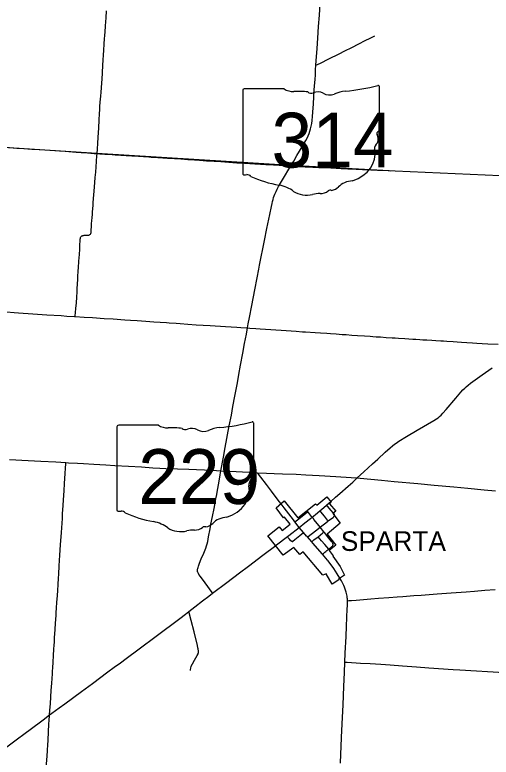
# Model space of a CAD drawing. Extents: x 9078 to 9739, y 4248 to 4966.
# Drawn here: x 9527 to 9587.6, y 4332.5 to 4427 of the extents above; entities that cross this region are included whole.
import ezdxf

# ---------------------------------------------------------------- set-up
doc = ezdxf.new("R2010")
doc.units = 0
for name, color, linetype in [('GM_X_City_Street', 7, 'Continuous'), ('GM_X_Corporation', 7, 'Continuous'), ('GM_X_Corporation_Text', 7, 'Continuous'), ('GM_X_County_Road', 7, 'Continuous'), ('GM_X_State_Route', 7, 'Continuous'), ('GM_X_State_Shield', 7, 'Continuous'), ('GM_X_Township', 7, 'Continuous'), ('GM_X_Township_Road', 7, 'Continuous')]:
    doc.layers.add(name, color=color, linetype=linetype)

msp = doc.modelspace()

# ---------------------------------------------------------------- linework, layer by layer
at = {"layer": 'GM_X_City_Street'}
for points in [[(9567.668, 4363.262), (9567.67, 4363.274), (9567.671, 4363.287), (9567.672, 4363.296), (9567.672, 4363.301), (9567.672, 4363.312), (9567.671, 4363.327), (9567.667, 4363.353), (9567.658, 4363.386), (9567.651, 4363.406), (9567.64, 4363.436), (9567.631, 4363.452), (9567.624, 4363.467), (9567.608, 4363.493), (9567.581, 4363.53), (9567.548, 4363.574), (9567.257, 4363.898), (9566.779, 4364.431), (9566.642, 4364.585)], [(9562.627, 4362.464), (9563.108, 4362.841), (9564.229, 4363.711), (9564.233, 4363.714), (9564.24, 4363.718), (9564.247, 4363.72), (9564.252, 4363.722), (9564.256, 4363.723), (9564.262, 4363.725), (9564.275, 4363.724)], [(9564.802, 4363.05), (9564.75, 4363.118), (9564.337, 4363.661), (9564.306, 4363.698), (9564.303, 4363.703), (9564.299, 4363.707), (9564.291, 4363.714), (9564.288, 4363.717), (9564.284, 4363.72), (9564.275, 4363.724)], [(9565.839, 4361.78), (9565.709, 4361.944), (9565.05, 4362.771), (9564.983, 4362.857), (9564.942, 4362.904), (9564.905, 4362.946), (9564.861, 4362.993), (9564.802, 4363.05)], [(9566.862, 4362.566), (9566.786, 4362.66), (9566.38, 4363.162), (9565.913, 4363.719), (9565.792, 4363.863)], [(9566.862, 4362.566), (9567.153, 4362.782), (9567.481, 4363.024), (9567.565, 4363.102), (9567.584, 4363.121), (9567.608, 4363.147), (9567.624, 4363.169), (9567.644, 4363.204), (9567.652, 4363.219), (9567.657, 4363.231), (9567.66, 4363.24), (9567.665, 4363.253), (9567.668, 4363.262)], [(9565.839, 4361.78), (9565.867, 4361.801), (9566.377, 4362.192), (9566.761, 4362.491), (9566.862, 4362.566)], [(9564.213, 4360.524), (9564.322, 4360.607), (9565.226, 4361.3), (9565.839, 4361.78)], [(9565.57, 4360.564), (9566.192, 4361.065), (9566.315, 4361.177)], [(9566.315, 4361.177), (9565.839, 4361.78)], [(9567.471, 4359.47), (9567.478, 4359.494), (9567.483, 4359.523), (9567.485, 4359.557), (9567.484, 4359.588), (9567.478, 4359.64), (9567.471, 4359.673), (9567.46, 4359.704), (9567.443, 4359.737), (9567.42, 4359.778), (9567.368, 4359.847), (9567.254, 4359.999), (9567.12, 4360.168), (9566.767, 4360.608), (9566.639, 4360.775), (9566.417, 4361.053), (9566.315, 4361.177)], [(9562.266, 4359.955), (9562.243, 4359.957), (9562.23, 4359.96), (9562.213, 4359.965), (9562.203, 4359.968), (9562.191, 4359.974), (9562.178, 4359.981), (9562.169, 4359.987), (9562.152, 4360), (9562.132, 4360.017), (9562.103, 4360.044), (9562.086, 4360.061), (9562.067, 4360.083), (9561.939, 4360.23), (9561.786, 4360.427), (9561.663, 4360.585)], [(9562.266, 4359.955), (9562.28, 4359.956), (9562.294, 4359.956), (9562.31, 4359.958), (9562.323, 4359.961), (9562.33, 4359.962), (9562.337, 4359.965), (9562.345, 4359.97), (9562.35, 4359.973), (9562.357, 4359.978), (9562.363, 4359.983), (9562.629, 4360.207), (9563.236, 4360.701), (9563.71, 4361.106)], [(9564.758, 4359.906), (9564.86, 4359.989), (9565.051, 4360.146), (9565.57, 4360.564)], [(9566.921, 4358.981), (9566.436, 4359.55), (9565.997, 4360.043), (9565.8, 4360.283), (9565.57, 4360.564)], [(9566.921, 4358.981), (9567.329, 4359.297), (9567.43, 4359.39), (9567.454, 4359.424), (9567.462, 4359.444), (9567.471, 4359.47)], [(9566.124, 4358.332), (9566.262, 4358.44), (9566.445, 4358.595), (9566.567, 4358.699), (9566.702, 4358.809), (9566.921, 4358.981)]]:
    msp.add_lwpolyline(points, dxfattribs=at)
at = {"layer": 'GM_X_Corporation'}
msp.add_lwpolyline([(9566.167, 4355.686), (9563.694, 4358.633), (9563.248, 4358.28), (9562.487, 4359.202), (9561.141, 4358.229), (9559.186, 4360.654), (9560.641, 4361.807), (9561.01, 4361.336), (9562.002, 4362.166), (9561.309, 4363.066), (9561.176, 4362.96), (9560.225, 4364.231), (9561.267, 4365.121), (9563.004, 4362.976), (9565.229, 4364.736), (9565.409, 4364.565), (9566.691, 4365.635), (9567.249, 4364.945), (9567.035, 4364.752), (9567.838, 4363.812), (9567.455, 4363.506), (9568.402, 4362.273), (9566.727, 4360.87), (9567.847, 4359.474), (9567.002, 4358.799), (9567.482, 4358.112), (9567.441, 4358.082), (9568.396, 4356.773), (9568.953, 4355.676), (9568.167, 4355.142), (9568.209, 4355.08), (9567.382, 4354.519), (9566.59, 4355.84)], close=True, dxfattribs=at)
at = {"layer": 'GM_X_County_Road'}
for points in [[(9525.856, 4410.11), (9527.247, 4410.016), (9528.147, 4409.955), (9529.128, 4409.889), (9530.082, 4409.829), (9530.787, 4409.783), (9531.457, 4409.737), (9532.684, 4409.66), (9533.39, 4409.614), (9533.874, 4409.572), (9534.772, 4409.505), (9535.427, 4409.455), (9536.245, 4409.394), (9537.063, 4409.334), (9537.447, 4409.309)], [(9537.447, 4409.309), (9537.799, 4409.287), (9538.454, 4409.249), (9539.354, 4409.19), (9539.763, 4409.165), (9541.155, 4409.074), (9541.891, 4409.026), (9542.71, 4408.97), (9543.364, 4408.927), (9544.018, 4408.886), (9544.345, 4408.865), (9545.164, 4408.814), (9546.392, 4408.733), (9547.292, 4408.681), (9548.121, 4408.629), (9549.012, 4408.569), (9549.83, 4408.515), (9550.485, 4408.471), (9551.386, 4408.412), (9552.368, 4408.342), (9553.186, 4408.286), (9555.233, 4408.157), (9556.215, 4408.088), (9557.525, 4408.003), (9558.917, 4407.925), (9559.9, 4407.869), (9561.293, 4407.792), (9562.098, 4407.735)], [(9570.559, 4368.037), (9571.408, 4368.831), (9572.5, 4369.824), (9573.161, 4370.439), (9574.126, 4371.328), (9574.736, 4371.876), (9575.048, 4372.141), (9575.305, 4372.341), (9575.505, 4372.481), (9575.851, 4372.698), (9576.828, 4373.302), (9578.163, 4374.103), (9580.285, 4375.35), (9580.636, 4375.564), (9580.84, 4375.704), (9581.035, 4375.857), (9581.216, 4376.026), (9581.441, 4376.266), (9581.869, 4376.765), (9583.094, 4378.198), (9583.735, 4378.945), (9584.004, 4379.252), (9584.231, 4379.484), (9584.41, 4379.651), (9584.659, 4379.861), (9584.984, 4380.11), (9586.453, 4381.158), (9587.726, 4382.057)], [(9531.394, 4337.879), (9531.443, 4338.436), (9531.504, 4339.335), (9531.618, 4341.006), (9531.681, 4341.908), (9531.756, 4343.098), (9531.783, 4343.506), (9531.805, 4343.834), (9531.861, 4344.651), (9531.909, 4345.387), (9531.958, 4346.288), (9531.983, 4346.697), (9532.013, 4347.187), (9532.043, 4347.678), (9532.118, 4348.742), (9532.176, 4349.56), (9532.239, 4350.541), (9532.26, 4350.868), (9532.305, 4351.521), (9532.348, 4352.176), (9532.408, 4353.076), (9532.456, 4353.73), (9532.501, 4354.466), (9532.541, 4355.285), (9532.568, 4355.776), (9532.622, 4356.841), (9532.71, 4358.233), (9532.804, 4359.541), (9532.908, 4361.096), (9533.032, 4362.895), (9533.07, 4363.468), (9533.139, 4364.532), (9533.19, 4365.268), (9533.267, 4366.413), (9533.325, 4367.313), (9533.396, 4368.623), (9533.441, 4369.297), (9533.474, 4369.85), (9533.482, 4369.99)], [(9530.696, 4326.773), (9530.739, 4327.396), (9530.805, 4328.295), (9530.863, 4329.074), (9530.923, 4330.094), (9530.994, 4331.155), (9531.027, 4331.646), (9531.095, 4332.628), (9531.15, 4333.375), (9531.192, 4334.109), (9531.22, 4334.592), (9531.282, 4335.819), (9531.329, 4336.637), (9531.359, 4337.291), (9531.379, 4337.7), (9531.394, 4337.879)]]:
    msp.add_lwpolyline(points, dxfattribs=at)
at = {"layer": 'GM_X_State_Route'}
for points in [[(9553.215, 4368.964), (9553.535, 4370.698), (9553.766, 4371.907), (9554.279, 4374.65), (9554.537, 4376.02), (9554.746, 4377.15), (9554.988, 4378.44), (9555.301, 4380.134), (9555.498, 4381.183), (9555.721, 4382.393), (9556.001, 4383.924), (9556.231, 4385.132), (9556.462, 4386.341), (9556.606, 4387.127), (9556.697, 4387.631), (9556.846, 4388.436), (9557.14, 4389.968), (9557.531, 4391.981), (9557.815, 4393.513), (9558.021, 4394.594), (9558.129, 4395.128), (9558.758, 4398.246), (9559.058, 4399.775), (9559.307, 4400.98), (9559.42, 4401.565), (9559.631, 4402.584), (9559.711, 4402.956), (9559.769, 4403.229), (9559.839, 4403.472), (9559.913, 4403.723), (9559.985, 4403.925), (9560.07, 4404.143), (9560.154, 4404.34), (9560.227, 4404.491), (9560.371, 4404.794), (9560.54, 4405.117), (9561.033, 4405.968), (9562.098, 4407.735), (9562.469, 4408.362), (9562.888, 4409.066), (9563.227, 4409.628), (9563.774, 4410.543), (9564.015, 4410.971), (9564.165, 4411.262), (9564.304, 4411.558), (9564.428, 4411.861), (9564.536, 4412.169), (9564.628, 4412.482), (9564.702, 4412.801), (9564.76, 4413.122), (9564.817, 4413.527), (9564.863, 4414.017), (9564.908, 4414.589), (9564.975, 4415.652), (9565.09, 4417.371), (9565.13, 4417.944), (9565.186, 4418.762), (9565.225, 4419.334), (9565.265, 4419.983), (9565.304, 4420.551), (9565.344, 4421.127), (9565.45, 4422.682), (9565.537, 4423.991), (9565.638, 4425.464), (9565.734, 4426.937), (9565.882, 4429.147)], [(9526.297, 4370.368), (9528.673, 4370.27), (9530.312, 4370.193), (9532.195, 4370.084), (9533.482, 4369.99), (9533.831, 4369.966), (9534.977, 4369.898), (9535.714, 4369.861), (9537.022, 4369.781), (9538.578, 4369.691), (9539.724, 4369.625), (9541.444, 4369.544), (9543.082, 4369.444), (9544.555, 4369.343), (9545.455, 4369.289), (9546.192, 4369.251), (9547.666, 4369.195), (9549.142, 4369.138), (9552.093, 4369.018), (9553.215, 4368.964)], [(9553.215, 4368.964), (9555.146, 4368.858), (9557.613, 4368.721), (9557.807, 4368.71)], [(9557.807, 4368.71), (9559.007, 4368.647), (9559.99, 4368.607), (9561.056, 4368.565), (9562.776, 4368.499), (9563.995, 4368.441), (9565.703, 4368.348), (9567.831, 4368.22), (9569.794, 4368.089), (9570.559, 4368.037)], [(9560.859, 4364.764), (9560.639, 4365.053), (9559.648, 4366.363), (9559.002, 4367.213), (9558.301, 4368.124), (9557.984, 4368.505), (9557.807, 4368.71)], [(9567.189, 4365.052), (9567.788, 4365.578), (9568.341, 4366.076), (9569.4, 4367.001), (9569.995, 4367.521), (9570.21, 4367.712), (9570.39, 4367.878), (9570.559, 4368.037)], [(9570.559, 4368.037), (9570.939, 4368.01), (9573.634, 4367.747), (9575.269, 4367.601), (9578.285, 4367.315), (9580.327, 4367.126), (9582.858, 4366.892), (9584.651, 4366.727), (9586.691, 4366.542), (9588.159, 4366.411)], [(9566.971, 4364.87), (9567.189, 4365.052)], [(9560.184, 4359.448), (9560.294, 4359.529), (9561.663, 4360.585), (9561.846, 4360.727), (9563.168, 4361.749), (9563.895, 4362.321), (9564.599, 4362.887), (9564.802, 4363.05), (9565.239, 4363.401), (9565.792, 4363.863), (9566.311, 4364.297), (9566.642, 4364.585), (9566.971, 4364.87)], [(9566.851, 4357.486), (9566.787, 4357.565), (9566.124, 4358.332), (9564.922, 4359.719), (9564.758, 4359.906), (9564.213, 4360.524), (9564.113, 4360.637), (9563.71, 4361.106), (9563.168, 4361.749), (9562.627, 4362.464), (9562.453, 4362.694), (9561.271, 4364.248), (9560.859, 4364.764)], [(9525.974, 4333.835), (9527.164, 4334.711), (9528.282, 4335.543), (9528.938, 4336.036), (9530.577, 4337.271), (9531.394, 4337.879), (9531.696, 4338.103), (9532.623, 4338.781), (9533.355, 4339.308), (9535.47, 4340.866), (9536.853, 4341.892), (9538.836, 4343.352), (9539.626, 4343.939), (9540.422, 4344.518), (9541.145, 4345.059), (9542.802, 4346.288), (9544.98, 4347.898), (9547.992, 4350.153), (9548.702, 4350.712), (9549.112, 4351.027), (9549.898, 4351.653), (9550.869, 4352.413), (9551.651, 4353.013), (9552.141, 4353.382), (9553.95, 4354.742), (9555.588, 4355.982), (9556.699, 4356.829), (9558.542, 4358.208), (9560.184, 4359.448)], [(9568.362, 4355.271), (9568.005, 4355.852), (9567.566, 4356.517), (9567.354, 4356.829), (9567.075, 4357.208), (9566.851, 4357.486)], [(9568.426, 4331.738), (9568.464, 4332.885), (9568.493, 4333.867), (9568.55, 4335.011), (9568.623, 4336.731), (9568.747, 4339.188), (9568.847, 4341.482), (9568.919, 4343.284), (9568.98, 4344.607), (9569.033, 4345.741), (9569.134, 4347.87), (9569.186, 4349.181), (9569.29, 4351.385), (9569.308, 4351.768), (9569.312, 4352.033), (9569.319, 4352.331), (9569.319, 4352.417), (9569.319, 4352.444), (9569.316, 4352.535), (9569.305, 4352.659), (9569.287, 4352.799), (9569.262, 4352.975), (9569.226, 4353.156), (9569.186, 4353.338), (9569.141, 4353.52), (9569.072, 4353.754), (9568.94, 4354.143), (9568.861, 4354.334), (9568.777, 4354.521), (9568.657, 4354.757), (9568.55, 4354.959), (9568.362, 4355.271)]]:
    msp.add_lwpolyline(points, dxfattribs=at)
at = {"layer": 'GM_X_State_Shield'}
for p, q in [((9555.977, 4417.368), (9555.977, 4406.802)), ((9561.245, 4417.55), (9556.149, 4417.55)), ((9573.379, 4412.285), (9573.379, 4417.812)), ((9573.378, 4412.286), (9573.379, 4412.285)), ((9539.983, 4374.556), (9539.983, 4363.99)), ((9545.251, 4374.738), (9540.155, 4374.738)), ((9557.385, 4369.473), (9557.385, 4375)), ((9557.384, 4369.474), (9557.385, 4369.473))]:
    msp.add_line(p, q, dxfattribs=at)
for centre, major_axis, start_param, end_param in [((9567.18, 4431.956), (18.455, 0), 4.814394, 5.042369), ((9573.186, 4417.835), (0.194, 0), 6.141152, 7.989035), ((9556.177, 4417.391), (0.202, 0), 1.712693, 3.28349), ((9562.459, 4418.777), (1.955, 0), 4.042523, 4.731795), ((9563.107, 4411.618), (7.02, 0), 1.404758, 1.657858), ((9564.701, 4417.446), (0.564, 0), 3.836095, 5.185415), ((9565.529, 4416.224), (1.173, 0), 0.950623, 2.079405), ((9567.043, 4417.899), (1.411, 0), 4.081561, 5.145723), ((9569.534, 4414.323), (3.713, 0), 1.699011, 2.107814), ((9573.173, 4412.263), (0.207, 0), 5.05454, 6.418171), ((9573.335, 4411.879), (0.3, 0), 1.883978, 3.671073), ((9571.427, 4411.18), (1.8, 0), 5.934695, 6.695948), ((9574.073, 4409.971), (1.309, 0), 2.387724, 3.262537), ((9568.214, 4409.268), (4.616, 0), 5.101752, 6.440018), ((9556.179, 4406.779), (0.203, 0), 3.00124, 4.508301), ((9556.209, 4407.86), (1.552, 0), 4.665946, 4.897461), ((9556.527, 4406.192), (0.56, 0), 0.519207, 1.627899), ((9563.593, 4415.686), (13.327, 0), 4.195997, 4.488961), ((9570.161, 4403.835), (2.528, 0), 1.647645, 2.488434), ((9559.62, 4402.055), (4.17, 0), 0.823519, 1.323587), ((9567.127, 4404.325), (0.397, 0), 1.147584, 2.315152), ((9566.958, 4405.778), (1.491, 0), 4.937069, 5.64225), ((9564.129, 4406.14), (2.646, 0), 4.026481, 4.996735), ((9565.658, 4402.487), (2.174, 0), 1.495662, 1.94098), ((9565.852, 4405.349), (1.41, 0), 4.691044, 5.507374), ((9540.183, 4374.579), (0.202, 0), 1.712693, 3.28349), ((9546.465, 4375.965), (1.955, 0), 4.042523, 4.731795), ((9547.113, 4368.806), (7.02, 0), 1.404758, 1.657858), ((9549.535, 4373.412), (1.173, 0), 0.950623, 2.079405), ((9553.54, 4371.511), (3.713, 0), 1.699011, 2.107814), ((9551.187, 4389.144), (18.455, 0), 4.814394, 5.042369), ((9557.192, 4375.023), (0.194, 0), 6.141152, 7.989035), ((9548.707, 4374.634), (0.564, 0), 3.836095, 5.185415), ((9551.049, 4375.087), (1.411, 0), 4.081561, 5.145723), ((9557.341, 4369.067), (0.3, 0), 1.883978, 3.671073), ((9555.433, 4368.368), (1.8, 0), 5.934695, 6.695948), ((9557.179, 4369.451), (0.207, 0), 5.05454, 6.418171), ((9558.079, 4367.16), (1.309, 0), 2.387724, 3.262537), ((9552.22, 4366.456), (4.616, 0), 5.101752, 6.440018), ((9540.185, 4363.967), (0.203, 0), 3.00124, 4.508301), ((9540.215, 4365.048), (1.552, 0), 4.665946, 4.897461), ((9540.533, 4363.38), (0.56, 0), 0.519207, 1.627899), ((9547.599, 4372.874), (13.327, 0), 4.195997, 4.488961), ((9543.626, 4359.243), (4.17, 0), 0.823519, 1.323587), ((9550.964, 4362.966), (1.491, 0), 4.937069, 5.64225), ((9554.167, 4361.024), (2.528, 0), 1.647645, 2.488434), ((9548.135, 4363.328), (2.646, 0), 4.026481, 4.996735), ((9549.664, 4359.675), (2.174, 0), 1.495662, 1.94098), ((9549.858, 4362.537), (1.41, 0), 4.691044, 5.507374), ((9551.133, 4361.513), (0.397, 0), 1.147584, 2.315152)]:
    msp.add_ellipse(centre, major_axis=major_axis, ratio=0.8, start_param=start_param, end_param=end_param, dxfattribs=at)
at = {"layer": 'GM_X_Township'}
msp.add_lwpolyline([(9646.564, 4403.186), (9632.593, 4403.992), (9619.889, 4404.725), (9619.129, 4404.769), (9590.635, 4406.413), (9575.396, 4407.069), (9562.089, 4407.805), (9537.409, 4409.337), (9510.323, 4411.058), (9511.38, 4427.966), (9511.83, 4435.772), (9511.888, 4436.239), (9513.121, 4453.992), (9514.674, 4478.861), (9516.207, 4506.231), (9517.263, 4528.671), (9517.499, 4532.736), (9518.307, 4546.633)], dxfattribs=at)
at = {"layer": 'GM_X_Township_Road'}
for points in [[(9537.447, 4409.309), (9537.495, 4409.895), (9537.539, 4410.632), (9537.587, 4411.369), (9537.664, 4412.597), (9537.726, 4413.58), (9537.771, 4414.399), (9537.798, 4414.891), (9537.821, 4415.3), (9537.859, 4415.87), (9537.886, 4416.223), (9537.913, 4416.627), (9537.949, 4417.113), (9538.035, 4418.292), (9538.079, 4418.83), (9538.134, 4419.542), (9538.203, 4420.601), (9538.236, 4421.175), (9538.283, 4421.911), (9538.315, 4422.401), (9538.367, 4423.302), (9538.404, 4423.876), (9538.435, 4424.367), (9538.46, 4424.775), (9538.516, 4425.591), (9538.553, 4426.081), (9538.589, 4426.572), (9538.649, 4427.473)], [(9565.304, 4420.551), (9565.869, 4420.82), (9566.944, 4421.35), (9568.267, 4422.009), (9568.999, 4422.382), (9569.876, 4422.83), (9570.754, 4423.278), (9571.558, 4423.688), (9572.222, 4424.004), (9572.793, 4424.277)], [(9534.673, 4388.579), (9534.682, 4388.684), (9534.719, 4389.092), (9534.758, 4389.583), (9534.81, 4390.32), (9534.857, 4391.058), (9534.897, 4391.713), (9534.923, 4392.122), (9534.991, 4393.35), (9535.017, 4393.76), (9535.049, 4394.25), (9535.09, 4394.905), (9535.126, 4395.478), (9535.138, 4395.642), (9535.164, 4396.052), (9535.192, 4396.46), (9535.236, 4397.142), (9535.272, 4397.735), (9535.301, 4398.158), (9535.315, 4398.403), (9535.335, 4398.566), (9535.355, 4398.646), (9535.39, 4398.718), (9535.439, 4398.782), (9535.502, 4398.831), (9535.575, 4398.868), (9535.655, 4398.892), (9535.736, 4398.906), (9535.819, 4398.913), (9536.229, 4398.911), (9536.313, 4398.914), (9536.394, 4398.927), (9536.467, 4398.957), (9536.535, 4399), (9536.593, 4399.06), (9536.64, 4399.136), (9536.687, 4399.268), (9536.696, 4399.367), (9536.714, 4399.646), (9536.728, 4399.938), (9536.741, 4400.253), (9536.759, 4400.513), (9536.773, 4400.66), (9536.781, 4400.802), (9536.81, 4401.124), (9536.855, 4401.62), (9536.87, 4401.863), (9536.938, 4402.762), (9536.944, 4402.844), (9536.966, 4403.09), (9537.053, 4404.071), (9537.131, 4405.054), (9537.226, 4406.281), (9537.281, 4406.932), (9537.386, 4408.323), (9537.434, 4409.06), (9537.442, 4409.224), (9537.447, 4409.309)], [(9562.098, 4407.735), (9562.704, 4407.693), (9563.195, 4407.667), (9563.933, 4407.633), (9564.916, 4407.588), (9565.654, 4407.554), (9566.31, 4407.527), (9567.211, 4407.481), (9568.522, 4407.423), (9569.341, 4407.386), (9570.406, 4407.341), (9571.226, 4407.308), (9572.291, 4407.259), (9573.124, 4407.219), (9573.766, 4407.188), (9574.503, 4407.146), (9574.817, 4407.133)], [(9520.906, 4389.467), (9521.005, 4389.462), (9521.496, 4389.441), (9522.15, 4389.407), (9522.559, 4389.384), (9523.296, 4389.336), (9523.951, 4389.295), (9525.015, 4389.222), (9525.915, 4389.161), (9526.897, 4389.098), (9527.47, 4389.063), (9529.27, 4388.937), (9531.071, 4388.814), (9532.871, 4388.691), (9533.607, 4388.64), (9534.59, 4388.583), (9534.673, 4388.579)], [(9534.673, 4388.579), (9535.818, 4388.505), (9536.882, 4388.441), (9538.356, 4388.347), (9539.502, 4388.27), (9540.975, 4388.167), (9541.712, 4388.12)], [(9541.712, 4388.12), (9542.53, 4388.068), (9543.675, 4387.986), (9544.657, 4387.918), (9545.475, 4387.861), (9546.294, 4387.808), (9546.621, 4387.784), (9547.52, 4387.717), (9548.011, 4387.682), (9548.992, 4387.613), (9550.053, 4387.54), (9550.948, 4387.485), (9551.845, 4387.424), (9553.775, 4387.302), (9554.524, 4387.252), (9555.243, 4387.212), (9555.736, 4387.177), (9556.45, 4387.137), (9556.606, 4387.127)], [(9556.606, 4387.127), (9556.892, 4387.108), (9557.636, 4387.051), (9558.219, 4387.021), (9558.898, 4386.976), (9560.869, 4386.841), (9562.794, 4386.7), (9563.608, 4386.645), (9563.958, 4386.619), (9565.192, 4386.539), (9565.875, 4386.494), (9566.7, 4386.444), (9567.167, 4386.414), (9567.886, 4386.366), (9568.625, 4386.313), (9569.128, 4386.278), (9569.887, 4386.223), (9570.601, 4386.173), (9571.46, 4386.112), (9572.215, 4386.061), (9572.542, 4386.04), (9572.952, 4386.016), (9573.524, 4385.977), (9574.259, 4385.924), (9574.994, 4385.873), (9575.403, 4385.847), (9575.812, 4385.823), (9576.63, 4385.772), (9577.612, 4385.71), (9578.021, 4385.684), (9578.512, 4385.659), (9578.921, 4385.633), (9579.412, 4385.597), (9580.066, 4385.552), (9580.558, 4385.526), (9581.213, 4385.492), (9581.541, 4385.472), (9581.949, 4385.448), (9582.765, 4385.4), (9583.256, 4385.367), (9583.828, 4385.326), (9584.483, 4385.285), (9585.22, 4385.241), (9585.792, 4385.201), (9586.446, 4385.151), (9587.183, 4385.11), (9588.494, 4385.045)], [(9552.141, 4353.382), (9552.086, 4353.457), (9551.189, 4354.693), (9550.605, 4355.479), (9550.418, 4355.749), (9550.335, 4355.888), (9550.3, 4355.96), (9550.27, 4356.034), (9550.248, 4356.11), (9550.233, 4356.186), (9550.229, 4356.266), (9550.23, 4356.345), (9550.24, 4356.425), (9550.255, 4356.505), (9550.294, 4356.663), (9550.343, 4356.818), (9550.487, 4357.201), (9550.709, 4357.73), (9551.032, 4358.486), (9551.279, 4359.096), (9551.389, 4359.407), (9551.459, 4359.645), (9551.534, 4359.966), (9551.648, 4360.53), (9551.834, 4361.583), (9551.935, 4362.148), (9552.123, 4363.115), (9552.33, 4364.163), (9552.567, 4365.367), (9552.676, 4365.938), (9552.783, 4366.502), (9552.952, 4367.39), (9553.126, 4368.439), (9553.215, 4368.964)], [(9569.319, 4352.417), (9569.503, 4352.428), (9569.83, 4352.448), (9570.403, 4352.495), (9572.287, 4352.644), (9573.269, 4352.724), (9574.58, 4352.824), (9575.643, 4352.914), (9576.38, 4352.972), (9577.773, 4353.078), (9578.674, 4353.142), (9580.721, 4353.299), (9582.524, 4353.429), (9584.408, 4353.566), (9585.473, 4353.645), (9586.783, 4353.749), (9588.094, 4353.849)], [(9549.339, 4343.515), (9549.343, 4343.679), (9549.365, 4343.84), (9549.437, 4344.073), (9549.574, 4344.37), (9549.86, 4344.867), (9550.19, 4345.434), (9550.296, 4345.656), (9550.315, 4345.699), (9550.328, 4345.731), (9550.337, 4345.761), (9550.345, 4345.793), (9550.351, 4345.819), (9550.356, 4345.861), (9550.358, 4345.907), (9550.358, 4345.94), (9550.356, 4345.97), (9550.352, 4346.015), (9550.344, 4346.075), (9550.331, 4346.171), (9550.315, 4346.274), (9550.288, 4346.431), (9550.235, 4346.703), (9549.794, 4348.452), (9549.426, 4349.882), (9549.112, 4351.027)], [(9568.98, 4344.607), (9569.096, 4344.6), (9569.278, 4344.59), (9570.979, 4344.488), (9572.204, 4344.406), (9573.556, 4344.324), (9574.751, 4344.242), (9576.314, 4344.132), (9578.112, 4344), (9579.666, 4343.89), (9582.774, 4343.681), (9583.592, 4343.628), (9589.238, 4343.271)]]:
    msp.add_lwpolyline(points, dxfattribs=at)

# ---------------------------------------------------------------- texts
at = {"layer": 'GM_X_Corporation_Text'}
msp.add_text('SPARTA', height=2.5, rotation=0.00001, dxfattribs=at).set_placement((9568.469, 4358.753))
at = {"layer": 'GM_X_State_Shield'}
for s, p in [('314', (9559.646, 4407.547)), ('229', (9542.683, 4364.735))]:
    msp.add_text(s, height=6.961, dxfattribs=at).set_placement(p)

doc.saveas('drawing.dxf')
